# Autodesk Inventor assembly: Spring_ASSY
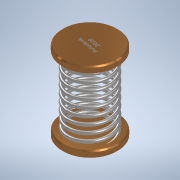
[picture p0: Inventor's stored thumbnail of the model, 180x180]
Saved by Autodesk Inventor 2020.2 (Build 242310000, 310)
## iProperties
Created: 2020-01
Part Number: Spring_ASSY
Document SubType Name: Assembly
Designer: thira
Author: thira
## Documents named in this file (3)
- F:\99.โปรแกรมอัดหน้าจอ\Synergysoft\Adaptive_Spring\Spring_ASSY.iam
- F:\99.โปรแกรมอัดหน้าจอ\Synergysoft\Adaptive_Spring\Plate_Spring.ipt
- F:\99.โปรแกรมอัดหน้าจอ\Synergysoft\Adaptive_Spring\Adaptive_Spring.ipt
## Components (3 placed, 2 different names)
1. Plate_Spring:1 — Mate:2, Mate:3, Mate:4, Mate:5
2. Plate_Spring:2 — Mate:4, Mate:5, Mate:6
3. Adaptive_Spring:1 — Mate:2, Mate:3, Mate:6
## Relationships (5: Mate 5)
- Mate:2: Plate_Spring:1 ↔ Adaptive_Spring:1
- Mate:3: Plate_Spring:1 ↔ Adaptive_Spring:1
- Mate:4: Plate_Spring:1 ↔ Plate_Spring:2
- Mate:5: Plate_Spring:1 ↔ Plate_Spring:2
- Mate:6: Plate_Spring:2 ↔ Adaptive_Spring:1
